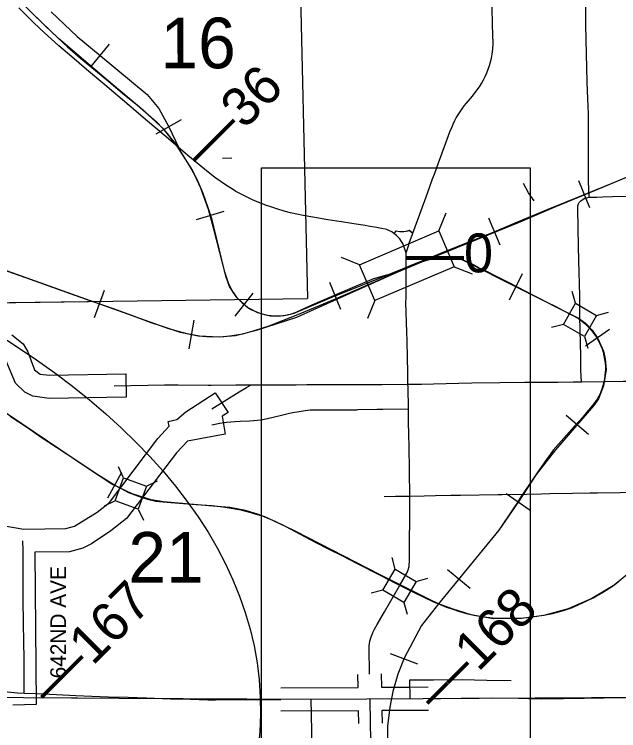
# Model space of a CAD drawing. Extents: x 10133 to 81668, y 5524 to 11018.
# Drawn here: x 15654.6 to 15848.7, y 8429.5 to 8659.6 of the extents above; entities that cross this region are included whole.
import ezdxf

# ---------------------------------------------------------------- set-up
doc = ezdxf.new("R2010")
doc.units = 0
for name, color, linetype in [('Default', 7, 'Continuous'), ('DsnShtRevisedText', 7, 'Continuous'), ('dsnTextFinalPlan', 7, 'Continuous'), ('trf_Signal_(Temp)_Layout', 7, 'Continuous')]:
    doc.layers.add(name, color=color, linetype=linetype)

msp = doc.modelspace()

# ---------------------------------------------------------------- linework, layer by layer
at = {"layer": 'Default'}
for p, q in [((15679.21, 8642.76), (15685.18, 8649.99)), ((15700.19, 8621.19), (15708.35, 8625.83)), ((15839.45, 8597.41), (15835.89, 8606.08)), ((15713.08, 8593.67), (15722.05, 8596.42)), ((15790.93, 8590.04), (15793.26, 8595.84)), ((15810.59, 8585.47), (15806.99, 8594.12)), ((15765.45, 8579.15), (15759.65, 8581.48)), ((15795.84, 8578.54), (15801.64, 8576.21)), ((15813.59, 8567.93), (15817.81, 8576.31)), ((15759.42, 8564.79), (15755.88, 8573.48)), ((15680.42, 8562.2), (15683.55, 8571.04)), ((15725.58, 8562.66), (15731.33, 8570.07)), ((15834.8, 8566.81), (15833.78, 8570.58)), ((15770.36, 8567.66), (15768.03, 8561.86)), ((15841.59, 8562.91), (15845.37, 8563.93)), ((15710.79, 8552.11), (15712.41, 8561.34)), ((15830.91, 8560.02), (15827.13, 8559)), ((15838, 8553.09), (15845.68, 8558.47)), ((15837.69, 8556.12), (15838.71, 8552.35)), ((15831.84, 8530.87), (15838.94, 8524.75)), ((15684.67, 8504.31), (15689.15, 8512.54)), ((15689.69, 8510.7), (15688.03, 8514.24)), ((15697.06, 8508.05), (15700.6, 8509.72)), ((15812.56, 8505.67), (15820.3, 8500.38)), ((15687.04, 8503.34), (15683.5, 8501.67)), ((15694.41, 8500.69), (15696.07, 8497.15)), ((15776.89, 8481.41), (15775.89, 8485.2)), ((15793.75, 8481.27), (15801, 8475.32)), ((15783.65, 8477.48), (15787.43, 8478.48)), ((15772.95, 8474.65), (15769.17, 8473.65)), ((15779.71, 8470.72), (15780.71, 8466.93)), ((15775.34, 8454.33), (15784.1, 8450.99))]:
    msp.add_line(p, q, dxfattribs=at)
for points in [[(15745.82, 8693.25), (15748.72, 8568.3)], [(15655.15, 8665.17), (15664.49, 8655.91), (15668.59, 8652.01), (15671.67, 8649.1), (15675.85, 8645.51), (15684.94, 8638.01), (15690.04, 8633.75), (15694.19, 8630.43), (15700.29, 8625.07), (15702.33, 8622.9), (15704.59, 8620.16), (15706.78, 8617.3), (15708.33, 8614.99), (15711.39, 8609.96), (15713.21, 8606.67), (15715.17, 8602.14), (15716.69, 8597.91), (15717.89, 8594), (15718.33, 8592.33), (15718.58, 8591.31), (15722.04, 8577.18), (15723.24, 8573.37), (15724.53, 8570.73), (15725.8, 8568.96), (15727.74, 8566.92), (15729.63, 8565.45), (15730.88, 8564.68), (15733.14, 8563.68), (15734.94, 8563.2), (15734.99, 8563.19), (15736.93, 8562.81), (15739.47, 8562.64), (15740.82, 8562.84), (15742.33, 8563.06), (15744.5, 8563.66), (15755.82, 8568.39), (15762.75, 8571.21), (15768.1, 8573.39), (15779.25, 8577.82), (15779.83, 8578.06)], [(15776.61, 8589.11), (15775.83, 8589.69), (15775.11, 8590.09), (15774.22, 8590.48), (15771.95, 8590.93), (15770.92, 8591.14), (15768.21, 8591.57), (15767.25, 8591.72), (15763.63, 8592.3), (15759.69, 8592.93), (15755.31, 8593.64), (15750.42, 8594.44), (15747.4, 8594.98), (15745.34, 8595.39), (15743.3, 8595.86), (15741.27, 8596.39), (15739.26, 8596.97), (15737.26, 8597.61), (15735.28, 8598.31), (15734.82, 8598.5), (15732.64, 8599.39), (15731.12, 8600), (15727.49, 8601.82), (15725.79, 8602.72), (15724.66, 8603.43), (15722.77, 8604.63), (15719.04, 8607.16), (15715.65, 8609.81), (15710.32, 8614.21), (15703.41, 8620.23), (15697.43, 8625.28), (15691.52, 8630.32), (15683.68, 8636.96), (15677.83, 8641.9), (15673.05, 8645.93), (15668.95, 8649.51), (15667.64, 8650.67), (15664.29, 8653.61), (15660.9, 8656.85), (15656.12, 8661.66)], [(15782.53, 8589.27), (15784.81, 8595.45), (15787.24, 8602.13), (15788.91, 8606.74), (15789.49, 8608.29), (15790.82, 8611.88), (15792.7, 8617.09), (15794.46, 8621.81), (15795.05, 8623.23), (15795.53, 8624.28), (15796, 8625.32), (15796.54, 8626.35), (15797.12, 8627.35), (15797.74, 8628.32), (15798.41, 8629.26), (15799.11, 8630.18), (15799.86, 8631.06), (15801.74, 8633.28), (15803.28, 8635.31), (15803.99, 8636.34), (15804.65, 8637.41), (15805.27, 8638.5), (15805.83, 8639.62), (15806.34, 8640.76), (15807.19, 8643.12), (15807.54, 8644.33), (15807.83, 8645.55), (15808.06, 8646.78), (15808.21, 8648.38), (15808.33, 8650.23), (15808.18, 8656.09), (15808.03, 8662.07)], [(15839.14, 8600.85), (15839.02, 8605.93), (15839.01, 8607.26), (15838.93, 8615.58), (15838.93, 8616.94), (15838.93, 8621.42), (15838.93, 8627.79), (15838.74, 8632.5), (15838.6, 8637.78), (15838.12, 8656.12), (15838.08, 8661.83), (15837.98, 8663.82)], [(15777.57, 8576.8), (15769.94, 8574.66), (15759.61, 8570.2), (15749.45, 8565.86), (15745.05, 8563.86), (15743.19, 8563.16), (15741.14, 8562.74), (15738.33, 8562.67), (15735.9, 8562.89), (15732.83, 8563.72), (15729.76, 8565.38), (15726.22, 8568.54), (15723.72, 8572.23), (15722.65, 8575.14), (15718.61, 8591.01), (15716.94, 8596.91), (15714.47, 8603.8), (15711.83, 8609.52), (15706.39, 8618.07), (15702.69, 8622.59), (15696.22, 8628.61), (15684.15, 8638.72), (15668.79, 8651.87), (15660.38, 8659.96)], [(15666.45, 8660.4), (15674.83, 8652.43), (15682.19, 8646.35), (15697.23, 8633.89), (15701.08, 8629.3), (15704.28, 8623.49), (15707.42, 8616.73), (15708.33, 8614.99), (15711.39, 8609.96), (15713.21, 8606.67), (15715.17, 8602.14), (15716.69, 8597.91), (15717.89, 8594), (15718.33, 8592.33), (15718.58, 8591.31), (15722.04, 8577.18), (15723.24, 8573.37), (15724.53, 8570.73), (15725.8, 8568.96), (15727.74, 8566.92), (15729.63, 8565.45), (15730.88, 8564.68), (15733.14, 8563.68), (15734.94, 8563.2), (15734.99, 8563.19), (15736.93, 8562.81), (15739.47, 8562.64), (15740.82, 8562.84), (15742.33, 8563.06), (15744.5, 8563.66), (15755.82, 8568.39), (15762.75, 8571.21), (15768.1, 8573.39), (15779.25, 8577.82), (15779.83, 8578.06)], [(15634.57, 8583.48), (15680.46, 8567.12), (15704.09, 8558.72), (15709.61, 8557.17), (15714.13, 8556.32), (15720.37, 8556.06), (15725.61, 8556.46), (15732.39, 8558.11), (15745.37, 8562.36), (15750.97, 8564.86), (15777.57, 8576.8), (15786.75, 8580.67), (15816.48, 8592.77), (15828.44, 8597.89), (15841.17, 8603.13), (15855, 8608.89), (15945.75, 8646.38)], [(15779.83, 8578.06), (15783.1, 8579.42), (15786.86, 8580.98), (15788.74, 8581.74), (15792.27, 8583.16), (15805.17, 8588.31), (15807.94, 8589.44), (15815.27, 8592.49), (15826.07, 8596.98), (15831.55, 8599.23), (15844.26, 8604.45), (15848.37, 8606.16), (15854.05, 8608.48), (15866.13, 8613.51), (15873.82, 8616.6), (15881.82, 8619.95), (15895.1, 8625.44), (15902.22, 8628.36), (15908.58, 8631.12), (15926.26, 8638.39), (15940.77, 8644.38), (15945.75, 8646.44)], [(15779.83, 8578.06), (15783.1, 8579.42), (15786.86, 8580.98), (15788.74, 8581.74), (15792.27, 8583.16), (15805.17, 8588.31), (15807.94, 8589.44), (15815.27, 8592.49), (15826.07, 8596.98), (15831.55, 8599.23), (15844.26, 8604.45), (15848.37, 8606.16), (15854.05, 8608.48), (15866.13, 8613.51), (15873.82, 8616.6), (15881.82, 8619.95), (15895.1, 8625.44), (15902.22, 8628.36), (15908.58, 8631.12), (15926.26, 8638.39), (15940.77, 8644.38), (15945.75, 8646.44)], [(15721.47, 8613.4), (15724.48, 8613.45)], [(15821.48, 8599.7), (15819.72, 8602.29), (15818.06, 8605.29)], [(15836.71, 8541.59), (15836.55, 8545.36), (15836.47, 8549.84), (15836.32, 8558.17), (15836.24, 8562.74), (15836.15, 8569.16), (15836.03, 8576.92), (15835.92, 8580.18), (15835.75, 8585.46), (15835.64, 8590.79), (15835.5, 8597.3), (15835.53, 8598.13), (15835.75, 8598.69), (15836.03, 8599.15), (15836.49, 8599.67), (15837.23, 8600.23), (15837.85, 8600.54), (15838.71, 8600.78), (15839.14, 8600.85)], [(15839.14, 8600.85), (15839.48, 8600.91), (15841.61, 8600.91), (15843.59, 8600.95), (15846.7, 8601.03), (15852.12, 8601.15)], [(15776.61, 8589.11), (15777.19, 8590.01), (15778.44, 8589.84), (15779.73, 8589.81), (15780.44, 8589.98), (15781.48, 8590.22), (15782.54, 8589.27)], [(15776.61, 8589.11), (15777.18, 8590.01), (15778.43, 8589.84), (15779.73, 8589.81), (15780.44, 8589.97), (15781.48, 8590.21), (15782.53, 8589.27)], [(15780.43, 8582.97), (15779.57, 8585.33), (15779.33, 8585.99), (15778.75, 8586.93), (15778.38, 8587.53), (15777.88, 8588.06), (15777.35, 8588.55), (15776.96, 8588.86), (15776.61, 8589.11)], [(15780.43, 8582.97), (15779.57, 8585.33), (15779.33, 8585.99), (15778.74, 8586.93), (15778.37, 8587.53), (15777.87, 8588.06), (15777.34, 8588.55), (15776.95, 8588.86), (15776.61, 8589.11)], [(15780.43, 8582.97), (15781.15, 8585.19), (15781.55, 8586.37), (15782.32, 8588.67), (15782.54, 8589.27)], [(15780.43, 8582.97), (15781.14, 8585.19), (15781.54, 8586.37), (15782.32, 8588.67), (15782.53, 8589.27)], [(15768.7, 8447.71), (15768.7, 8447.71), (15768.67, 8448.57), (15768.65, 8450.02), (15768.6, 8453.84), (15768.6, 8454.92), (15768.6, 8456.83), (15768.76, 8458.25), (15769.19, 8459.7), (15769.71, 8460.94), (15769.78, 8461.08), (15770.3, 8462.12), (15771.1, 8463.67), (15773.44, 8467.74), (15778.28, 8476.03), (15780.69, 8480.17), (15781.03, 8481.23), (15781.37, 8482.29), (15781.55, 8484.33), (15781.53, 8488.86), (15781.52, 8492.16), (15781.58, 8495.64), (15781.59, 8497.12), (15781.62, 8501.07), (15781.64, 8503.41), (15781.59, 8504.88), (15781.58, 8506.65), (15781.49, 8511.15), (15781.49, 8515.18), (15781.46, 8516.42), (15781.44, 8517.49), (15781.37, 8520.82), (15781.29, 8524.6), (15781.21, 8528.56), (15781.14, 8532.9), (15781.03, 8539.84), (15781.01, 8540.79), (15780.93, 8544.53), (15780.83, 8549.37), (15780.72, 8554.7), (15780.64, 8557.47), (15780.38, 8567), (15780.4, 8568.59), (15780.45, 8573.54), (15780.47, 8575.42), (15780.44, 8579.76), (15780.41, 8582.91), (15780.43, 8582.97)], [(15786.75, 8580.67), (15790.33, 8581.51), (15792.9, 8581.83), (15796.01, 8581.54), (15798.54, 8580.76), (15835.75, 8562.02), (15837.98, 8560.38), (15840.15, 8558.18), (15842.02, 8555.51), (15843.76, 8551.45), (15844.31, 8548.9), (15844.61, 8545.37), (15843.83, 8540.32), (15842.17, 8536.12), (15840.6, 8533.85), (15828.42, 8519.72), (15822.2, 8511.76), (15816.62, 8503.29), (15810.24, 8493.97), (15790.79, 8470.26), (15785.41, 8463.26), (15779.81, 8452.87), (15777.81, 8447.63), (15776.17, 8442.11), (15775.21, 8437.07), (15774.49, 8431), (15774.47, 8424.48)], [(15783.1, 8579.42), (15786.42, 8580.42), (15789.74, 8581.42), (15790.65, 8581.55), (15791.57, 8581.68), (15792.59, 8581.73), (15793.6, 8581.78), (15794.47, 8581.68), (15795.34, 8581.58), (15796.49, 8581.42), (15797.29, 8581.19), (15798.09, 8580.96), (15799.13, 8580.52), (15800.16, 8580.07), (15802.14, 8579.09), (15804.13, 8578.1), (15806.42, 8576.96), (15808.71, 8575.81), (15813.61, 8573.31), (15818.51, 8570.8), (15820.74, 8569.66), (15822.96, 8568.52), (15825.6, 8567.17), (15828.24, 8565.82), (15830.89, 8564.48), (15833.55, 8563.13), (15834.33, 8562.67), (15835.12, 8562.22), (15835.83, 8561.77), (15836.53, 8561.33), (15837.17, 8560.79), (15837.81, 8560.25), (15838.54, 8559.53), (15839.28, 8558.81), (15839.82, 8558.17), (15840.36, 8557.53), (15840.95, 8556.73), (15841.31, 8556.23), (15841.67, 8555.73), (15842.33, 8554.42), (15842.98, 8553.11), (15843.35, 8552.12), (15843.71, 8551.14), (15843.94, 8549.96), (15844.16, 8548.78), (15844.3, 8547.63), (15844.43, 8546.49), (15844.42, 8546.17), (15844.39, 8545.43), (15844.36, 8544.69), (15844.25, 8543.62), (15844.13, 8542.56), (15843.87, 8541.44), (15843.61, 8540.33), (15843.35, 8539.49), (15843.08, 8538.66), (15842.79, 8537.98), (15842.49, 8537.31), (15842.1, 8536.64), (15841.71, 8535.97), (15840.13, 8533.81), (15839.55, 8533.12), (15838.97, 8532.44), (15838.26, 8531.6), (15837.55, 8530.76), (15836.04, 8529.04), (15834.53, 8527.32), (15832.79, 8525.39), (15831.06, 8523.45), (15829.37, 8521.53), (15827.68, 8519.62), (15826.67, 8518.25), (15825.68, 8516.93), (15824.73, 8515.55), (15823.78, 8514.18), (15822.73, 8512.62), (15821.68, 8511.07), (15820.05, 8508.71), (15818.63, 8506.68), (15818.38, 8506.31), (15817.26, 8504.58), (15816.15, 8502.84), (15815.03, 8501.1), (15810.24, 8493.97), (15790.79, 8470.26), (15785.41, 8463.26), (15779.81, 8452.87), (15777.81, 8447.63), (15776.17, 8442.11), (15775.21, 8437.07), (15774.49, 8431), (15774.47, 8424.48)], [(15650.62, 8577.77), (15659.76, 8574.49), (15675.59, 8568.89), (15686.33, 8565.09), (15692.2, 8562.94), (15698.46, 8560.65), (15701.77, 8559.5), (15704.68, 8558.55), (15707.86, 8557.54), (15711.07, 8556.82), (15713.7, 8556.36), (15716.28, 8556.13), (15718.74, 8556.03), (15721.95, 8556.16), (15724.54, 8556.46), (15727.98, 8557.01), (15731.78, 8558), (15736.4, 8559.54), (15745.68, 8563.17), (15757.77, 8568.19), (15773.07, 8574.87), (15779.83, 8578.06)], [(15650.62, 8577.77), (15659.76, 8574.49), (15675.59, 8568.89), (15686.33, 8565.09), (15692.2, 8562.94), (15698.46, 8560.65), (15701.77, 8559.5), (15704.68, 8558.55), (15707.86, 8557.54), (15711.07, 8556.82), (15713.7, 8556.36), (15716.28, 8556.13), (15718.74, 8556.03), (15721.95, 8556.16), (15724.54, 8556.46), (15727.98, 8557.01), (15731.78, 8558), (15736.4, 8559.54), (15745.68, 8563.17), (15757.77, 8568.19), (15773.07, 8574.87), (15779.83, 8578.06)], [(15623.87, 8566.62), (15686.29, 8567.46), (15748.72, 8568.3)], [(15627.99, 8566.68), (15686.29, 8567.46)], [(15653.81, 8556.64), (15657.43, 8553.74), (15658.98, 8551.16), (15661.16, 8545.4), (15662.96, 8544.06), (15665.95, 8543.69), (15690.39, 8544.1), (15690.53, 8536.6), (15665.82, 8536.19), (15660.54, 8536.96), (15658.03, 8538.24), (15654.98, 8541.09), (15651.91, 8548.56)], [(15854.8, 8482.61), (15847.4, 8476.39), (15840.01, 8471.94), (15832.4, 8468.61), (15824.65, 8466.54), (15817.44, 8465.6), (15808.39, 8465.4), (15801.28, 8466.75), (15795.52, 8468.51), (15790.79, 8470.26), (15787.91, 8471.65), (15771.92, 8479.65), (15745.01, 8493.5), (15738.43, 8496.69), (15733.35, 8498.84), (15728.86, 8500.19), (15723.83, 8501.19), (15717.03, 8501.79), (15702.58, 8503.03), (15698.53, 8503.66), (15692.49, 8505.62), (15685.97, 8508.74), (15677.47, 8514.25), (15620.05, 8553)], [(15836.71, 8541.59), (15844.35, 8541.67), (15850.1, 8541.73), (15858.21, 8541.81), (15858.21, 8541.81), (15859.12, 8541.82), (15864.18, 8541.9), (15872.19, 8542.03)], [(15686.71, 8540.28), (15702.8, 8540.56), (15707.22, 8540.55), (15716.89, 8540.53), (15717.78, 8540.53), (15725.72, 8540.6), (15728.42, 8540.62), (15730.71, 8540.62)], [(15718.06, 8532.86), (15719.8, 8533.99), (15725.92, 8537.84), (15726.77, 8538.37), (15729.17, 8539.73), (15730.71, 8540.62)], [(15730.71, 8540.62), (15733.38, 8540.63), (15736.14, 8540.63), (15739.94, 8540.64), (15744.45, 8540.65), (15745.15, 8540.65), (15748.58, 8540.67), (15751.73, 8540.68), (15760.88, 8540.71), (15764.5, 8540.73), (15772.78, 8540.76), (15781, 8540.79), (15785.38, 8540.8), (15789.17, 8540.91), (15797.38, 8541.15), (15801.57, 8541.27), (15810.53, 8541.36), (15818.58, 8541.44), (15820.28, 8541.45), (15821.7, 8541.46), (15829.25, 8541.51), (15834.1, 8541.56), (15836.71, 8541.59)], [(15625.94, 8499.72), (15657.66, 8494.28), (15671.2, 8494.41), (15673.94, 8495.18), (15681.23, 8499.73), (15685.14, 8502.81), (15700.76, 8523.41), (15704.4, 8527.37), (15704.07, 8528.85), (15706.79, 8529.44), (15709.71, 8531.92), (15719.16, 8538.05), (15723.24, 8531.76), (15721.33, 8530.52), (15722.35, 8524.74), (15710.24, 8522.52), (15706.66, 8518.79), (15690.65, 8497.72), (15685.64, 8493.66), (15679.42, 8489.53), (15676.63, 8488.17), (15672.34, 8486.99), (15661.23, 8486.85), (15661.67, 8437.93), (15654.17, 8437.73)], [(15718.01, 8527.79), (15720.65, 8528.25), (15722.77, 8528.59), (15724.13, 8528.74), (15725.49, 8528.84), (15727.09, 8528.93), (15730.26, 8528.99), (15733.75, 8529.36), (15735.97, 8529.76), (15740.38, 8530.9), (15743, 8531.52), (15744.6, 8531.83), (15745.39, 8531.95), (15748.02, 8532.35), (15748.87, 8532.45), (15749.59, 8532.53), (15752.37, 8532.6), (15761.11, 8532.54), (15762.82, 8532.53), (15764.64, 8532.61), (15764.65, 8532.61), (15764.94, 8532.63), (15771.05, 8532.78), (15772.95, 8532.8), (15772.95, 8532.8), (15781.14, 8532.89)], [(15653.29, 8530.53), (15658.83, 8526.92), (15663.28, 8523.78), (15668.14, 8520.61), (15675.04, 8516.08), (15681.43, 8511.79), (15686.6, 8508.59), (15691.3, 8506.04), (15695.37, 8504.53), (15697.41, 8503.89), (15700.1, 8503.28), (15703.55, 8502.87), (15707.61, 8502.59), (15713, 8502.19), (15718.14, 8501.8), (15721.62, 8501.4), (15724.21, 8501.01), (15727.31, 8500.48), (15727.64, 8500.39), (15730.52, 8499.6), (15731.84, 8499.18), (15734.73, 8498.44), (15737.96, 8496.9), (15741.82, 8495.12), (15746.38, 8492.62), (15751.19, 8490.12), (15755.44, 8487.88), (15759.95, 8485.64), (15764.73, 8483.26), (15771.92, 8479.56), (15774.52, 8478.19), (15777.03, 8476.88), (15782.76, 8473.99), (15789.19, 8470.94), (15790.64, 8470.34), (15793.35, 8469.23), (15795.08, 8468.62), (15797.6, 8467.82), (15799.82, 8467.15), (15802.2, 8466.61), (15805.46, 8466.08), (15808.14, 8465.8), (15809.69, 8465.67), (15812.65, 8465.62), (15817.02, 8465.69), (15819.22, 8465.9), (15821.6, 8466.17), (15824.58, 8466.61), (15827.45, 8467.15), (15830.91, 8468.12), (15833.8, 8469.06), (15836.34, 8470.22), (15837.04, 8470.54), (15840.51, 8472.18), (15843.81, 8474.13), (15846.66, 8475.98), (15848.92, 8477.73)], [(15781.61, 8504.88), (15786.19, 8504.95), (15789.88, 8505.03), (15794.73, 8505.14), (15797.89, 8505.18), (15809.99, 8505.36), (15811.23, 8505.38), (15819.05, 8505.54), (15823.8, 8505.63), (15826.56, 8505.68), (15833.83, 8505.79), (15839.37, 8505.88), (15841.83, 8505.92), (15849.09, 8506.05), (15851.79, 8506.09), (15856.96, 8506.2), (15861.07, 8506.28), (15863.99, 8506.31), (15865.07, 8506.32), (15872.23, 8506.4), (15872.96, 8506.4)], [(15773.4, 8504.77), (15777.01, 8504.8), (15781.59, 8504.88), (15781.61, 8504.88)], [(15657.82, 8441.58), (15657.76, 8443.88), (15657.83, 8452.54), (15657.55, 8463.82), (15657.43, 8471.84), (15657.43, 8481.09), (15657.49, 8487.44), (15657.37, 8490.54)], [(15740.15, 8443.26), (15765.02, 8443.42), (15764.95, 8447.62)], [(15772.45, 8447.81), (15772.52, 8443.47), (15781.67, 8443.54), (15787.55, 8443.56)], [(15781.66, 8445.82), (15783.22, 8445.89), (15789.2, 8445.89), (15798.45, 8445.92), (15806.31, 8445.73), (15814.11, 8445.64)], [(15781.71, 8439.79), (15781.7, 8440.11), (15781.66, 8445.82)], [(15749.8, 8439.6), (15857.91, 8440.25), (15875.44, 8441.06)], [(15626.73, 8440.37), (15688.27, 8439.98), (15749.8, 8439.6)], [(15661.61, 8440.15), (15688.27, 8439.98), (15719.27, 8439.79)], [(15749.8, 8439.6), (15752.38, 8316.92)], [(15769.23, 8426.41), (15769.01, 8430.35), (15768.97, 8431.09), (15768.96, 8431.93), (15768.94, 8434.2), (15768.87, 8437.25), (15768.89, 8439.76)], [(15765.22, 8431.89), (15765.15, 8435.92), (15740.23, 8435.76)], [(15787.56, 8436.06), (15781.76, 8436.04), (15772.65, 8435.97), (15772.72, 8431.96)]]:
    msp.add_lwpolyline(points, dxfattribs=at)
for points in [[(15765.45, 8579.15), (15790.93, 8590.04), (15795.84, 8578.54), (15770.36, 8567.66)], [(15834.8, 8566.81), (15841.59, 8562.91), (15837.69, 8556.12), (15830.91, 8560.02)], [(15689.69, 8510.7), (15697.06, 8508.05), (15694.41, 8500.69), (15687.04, 8503.34)], [(15772.95, 8474.65), (15776.89, 8481.41), (15783.65, 8477.48), (15779.71, 8470.72)]]:
    msp.add_lwpolyline(points, close=True, dxfattribs=at)
at = {"layer": 'DsnShtRevisedText'}
msp.add_lwpolyline([(15646.88, 8442.53), (15655.7, 8441.66), (15657.82, 8441.58), (15661.74, 8441.42), (15668.21, 8441.14), (15674.38, 8440.83), (15679.56, 8440.59), (15684.86, 8440.43), (15691.18, 8440.28), (15697.03, 8440.12), (15704.77, 8439.81), (15711.12, 8439.63), (15716.76, 8439.48), (15719.27, 8439.49), (15724.28, 8439.51), (15736.09, 8439.54), (15740.19, 8439.51)], dxfattribs=at)
at = {"layer": 'dsnTextFinalPlan'}
msp.add_ellipse((15267.06, 8422.1), major_axis=(466.54, 18.24), ratio=0.458759, dxfattribs=at)
at = {"layer": 'trf_Signal_(Temp)_Layout'}
msp.add_lwpolyline([(15734, 8610.29), (15820.25, 8610.29), (15820.25, 8399.64), (15734, 8399.64)], close=True, dxfattribs=at)
msp.add_lwpolyline([(15787.56, 8439.81), (15791.59, 8439.86), (15798.14, 8439.97), (15799.47, 8439.98), (15803.2, 8440.02), (15807.7, 8440.06), (15816.45, 8439.97), (15819.69, 8439.91), (15823.76, 8439.78), (15828, 8439.82), (15830.94, 8439.85), (15837.63, 8440), (15841.24, 8440.06), (15843.91, 8440.1), (15857.91, 8440.25)], dxfattribs=at)

# ---------------------------------------------------------------- texts
at = {"layer": 'Default'}
for s, height, rotation, p in [('16', 16.25, 0.0278, (15701.56, 8642.26)), ('‒‒36', 12.5, 45, (15715.38, 8609.25)), ('21', 16.25, 0.0275, (15691.26, 8477.07)), ('642ND AVE', 5, 90, (15671.2, 8446.34)), ('‒‒167', 12.5, 45, (15666.65, 8436.98)), ('‒‒168', 12.5, 45, (15790.43, 8435.03))]:
    msp.add_text(s, height=height, rotation=rotation, dxfattribs=at).set_placement(p)
msp.add_text('‒‒0', height=12.5, dxfattribs=at).set_placement((15780.43, 8576.73))

doc.saveas('drawing.dxf')
